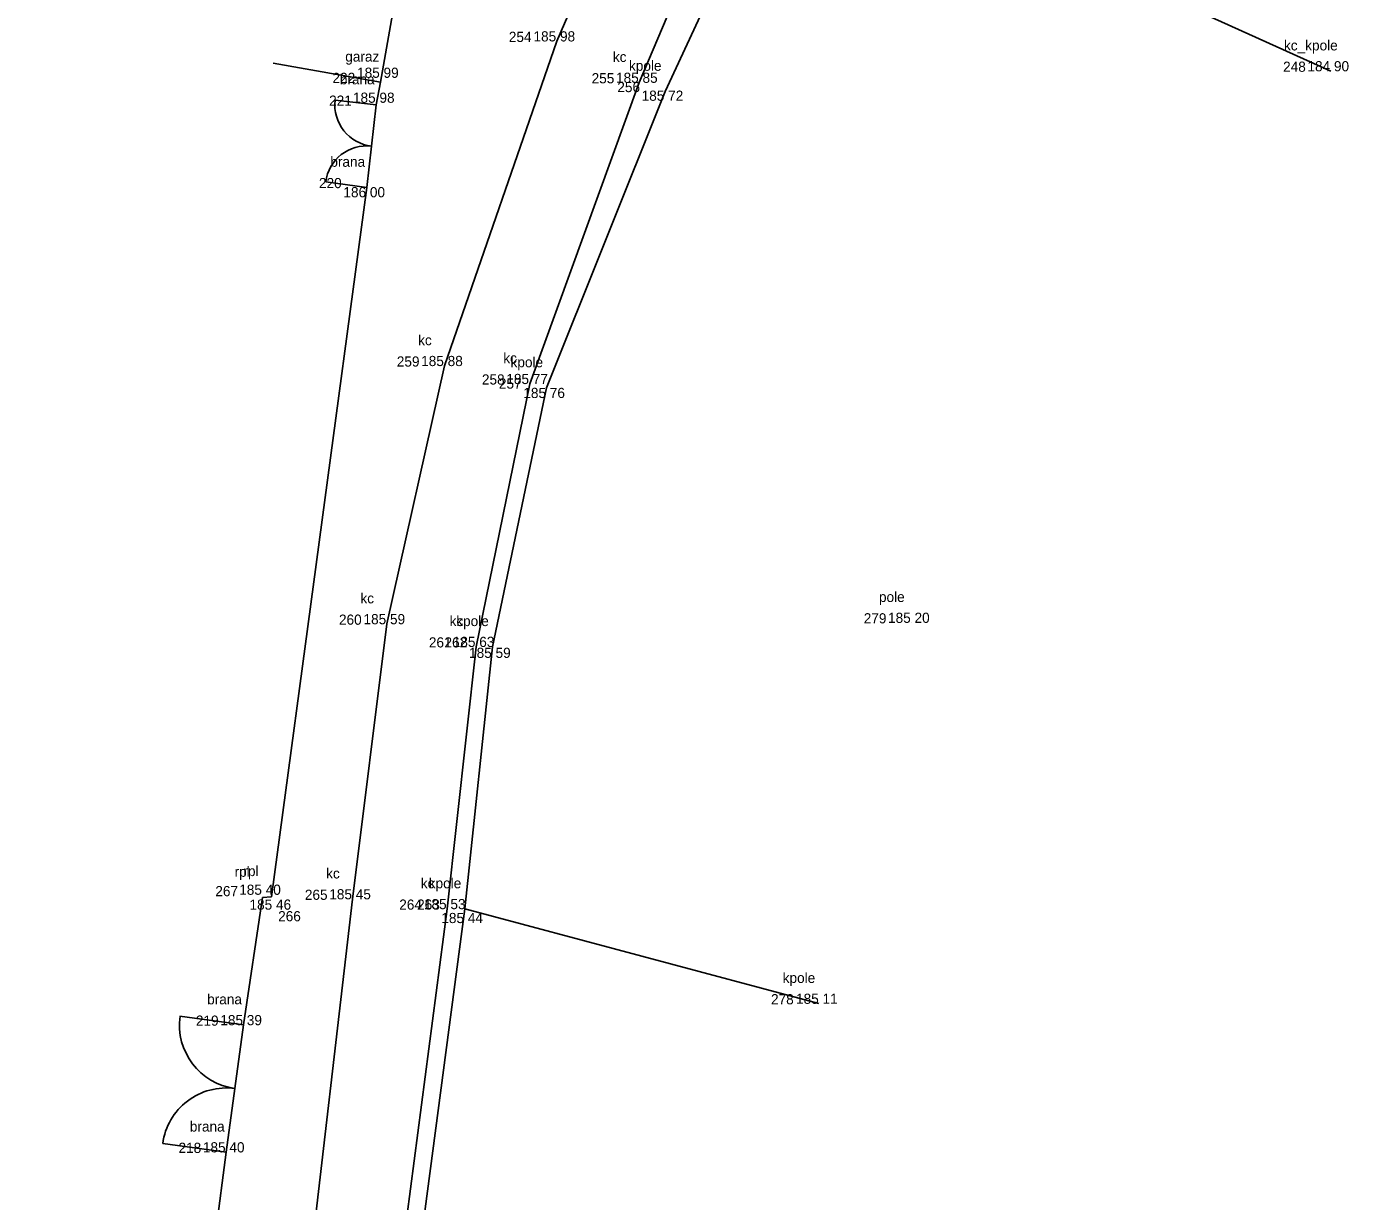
# Model space of a CAD drawing. Extents: x -598527 to -598215, y -1172822 to -1172560.
# Drawn here: x -598268.17 to -598229.21, y -1172645.27 to -1172610.63 of the extents above; entities that cross this region are included whole.
import ezdxf

# ---------------------------------------------------------------- set-up
doc = ezdxf.new("R2010")
doc.units = 0
for name, color, linetype in [('Body', 7, 'Continuous'), ('Body čísla', 7, 'Continuous'), ('Kody', 7, 'Continuous'), ('Kraj pole', 7, 'Continuous'), ('PATTERN_CLASS', 7, 'Continuous'), ('Ploty', 7, 'Continuous'), ('Výšky', 7, 'Continuous')]:
    doc.layers.add(name, color=color, linetype=linetype)

msp = doc.modelspace()

# ---------------------------------------------------------------- linework, layer by layer
at = {"layer": 'Body'}
for p, q in [((-598252.54, -1172611.06), (-598252.54, -1172611.06)), ((-598229.73, -1172611.94), (-598229.73, -1172611.94)), ((-598257.74, -1172612.27), (-598257.74, -1172612.27)), ((-598250.11, -1172612.28), (-598250.11, -1172612.28)), ((-598249.35, -1172612.54), (-598249.35, -1172612.54)), ((-598257.86, -1172612.94), (-598257.86, -1172612.94)), ((-598258.14, -1172615.37), (-598258.14, -1172615.37)), ((-598255.85, -1172620.63), (-598255.85, -1172620.63)), ((-598253.34, -1172621.16), (-598253.34, -1172621.16)), ((-598252.84, -1172621.28), (-598252.84, -1172621.28)), ((-598257.55, -1172628.24), (-598257.55, -1172628.24)), ((-598242.09, -1172628.2), (-598242.09, -1172628.2)), ((-598254.92, -1172628.91), (-598254.92, -1172628.91)), ((-598254.44, -1172628.91), (-598254.44, -1172628.91)), ((-598261.21, -1172636.3), (-598261.21, -1172636.3)), ((-598260.95, -1172636.28), (-598260.95, -1172636.28)), ((-598258.56, -1172636.35), (-598258.56, -1172636.35)), ((-598255.77, -1172636.64), (-598255.77, -1172636.64)), ((-598255.25, -1172636.64), (-598255.25, -1172636.64)), ((-598244.82, -1172639.43), (-598244.82, -1172639.43)), ((-598261.77, -1172640.06), (-598261.77, -1172640.06)), ((-598262.28, -1172643.81), (-598262.28, -1172643.81))]:
    msp.add_line(p, q, dxfattribs=at)
at = {"layer": 'Kraj pole'}
for p, q in [((-598249.35, -1172612.54), (-598245.7, -1172604.72)), ((-598252.84, -1172621.28), (-598249.35, -1172612.54)), ((-598254.44, -1172628.91), (-598252.84, -1172621.28)), ((-598255.25, -1172636.64), (-598254.44, -1172628.91)), ((-598256.79, -1172648.24), (-598255.25, -1172636.64)), ((-598255.25, -1172636.64), (-598244.82, -1172639.43))]:
    msp.add_line(p, q, dxfattribs=at)
at = {"layer": 'PATTERN_CLASS'}
for p, q in [((-598257.74, -1172612.27), (-598257.23, -1172609.4)), ((-598257.74, -1172612.27), (-598260.896, -1172611.709)), ((-598253.34, -1172621.16), (-598250.11, -1172612.28))]:
    msp.add_line(p, q, dxfattribs=at)
for points in [[(-598268.17, -1172706.75), (-598265.5, -1172685.75), (-598263.77, -1172672.23), (-598261.78, -1172661.56), (-598259.91, -1172647.93), (-598258.56, -1172636.35), (-598257.55, -1172628.24), (-598255.85, -1172620.63), (-598252.54, -1172611.06), (-598250.18, -1172605.62), (-598248.3, -1172599.38), (-598247.28, -1172594.11), (-598247.12, -1172592.75), (-598247.32, -1172591.46), (-598247.682, -1172590.57), (-598248.25, -1172589.72), (-598249.298, -1172588.918), (-598249.871, -1172588.59), (-598250.6, -1172588.3), (-598252.47, -1172587.89)], [(-598250.11, -1172612.28), (-598247.61, -1172606.36), (-598246.923, -1172605.269), (-598246.42, -1172604.864), (-598245.775, -1172604.644), (-598245.325, -1172604.707), (-598243.43, -1172605.57), (-598236.98, -1172608.66), (-598229.73, -1172611.94)], [(-598253.34, -1172621.16), (-598254.92, -1172628.91), (-598255.77, -1172636.64), (-598257.28, -1172648.19), (-598259.24, -1172661.8), (-598261.36, -1172673.07), (-598262.76, -1172685.61)]]:
    msp.add_lwpolyline(points, dxfattribs=at)
at = {"layer": 'Ploty'}
for p, q in [((-598257.86, -1172612.94), (-598257.74, -1172612.27)), ((-598257.86, -1172612.94), (-598259.075, -1172612.8)), ((-598258.14, -1172615.37), (-598257.86, -1172612.94)), ((-598258.14, -1172615.37), (-598259.352, -1172615.207)), ((-598260.95, -1172636.28), (-598258.14, -1172615.37)), ((-598261.77, -1172640.06), (-598261.21, -1172636.3)), ((-598260.95, -1172636.28), (-598261.21, -1172636.3)), ((-598261.77, -1172640.06), (-598263.645, -1172639.805)), ((-598262.28, -1172643.81), (-598261.77, -1172640.06)), ((-598262.28, -1172643.81), (-598264.155, -1172643.555)), ((-598262.77, -1172647.51), (-598262.28, -1172643.81))]:
    msp.add_line(p, q, dxfattribs=at)
for centre, radius, start, end in [((-598257.86, -1172612.94), 1.223, 173.427, 263.427), ((-598258.14, -1172615.37), 1.223, 83.427, 172.3461), ((-598261.77, -1172640.06), 1.892, 172.2553, 262.2553), ((-598262.28, -1172643.81), 1.892, 82.2553, 172.2553)]:
    msp.add_arc(centre, radius, start, end, dxfattribs=at)

# ---------------------------------------------------------------- texts
at = {"layer": 'Body čísla'}
for s, p in [('254', (-598253.954, -1172611.083)), ('248', (-598231.138, -1172611.963)), ('222', (-598259.151, -1172612.293)), ('255', (-598251.515, -1172612.303)), ('256', (-598250.757, -1172612.563)), ('221', (-598259.251, -1172612.963)), ('220', (-598259.55, -1172615.393)), ('259', (-598257.256, -1172620.653)), ('258', (-598254.748, -1172621.183)), ('257', (-598254.248, -1172621.303)), ('260', (-598258.96, -1172628.263)), ('279', (-598243.496, -1172628.223)), ('261', (-598256.311, -1172628.933)), ('262', (-598255.851, -1172628.933)), ('267', (-598262.604, -1172636.266)), ('265', (-598259.965, -1172636.373)), ('266', (-598260.752, -1172637.005)), ('264', (-598257.184, -1172636.663)), ('263', (-598256.657, -1172636.663)), ('278', (-598246.228, -1172639.453)), ('219', (-598263.176, -1172640.083)), ('218', (-598263.688, -1172643.833))]:
    msp.add_text(s, height=0.3, dxfattribs=at).set_placement(p)
at = {"layer": 'Kody'}
for s, p in [('kc', (-598250.888, -1172611.673)), ('kc_kpole', (-598231.111, -1172611.333)), ('garaz', (-598258.775, -1172611.663)), ('kpole', (-598250.414, -1172611.933)), ('brana', (-598258.935, -1172612.333)), ('brana', (-598259.215, -1172614.763)), ('kc', (-598256.628, -1172620.023)), ('kc', (-598254.118, -1172620.553)), ('kpole', (-598253.904, -1172620.673)), ('kc', (-598258.328, -1172627.633)), ('pole', (-598243.047, -1172627.593)), ('kc', (-598255.698, -1172628.303)), ('kpole', (-598255.504, -1172628.303)), ('rpl', (-598262.036, -1172635.693)), ('rpl', (-598261.776, -1172635.673)), ('kc', (-598259.338, -1172635.743)), ('kc', (-598256.548, -1172636.033)), ('kpole', (-598256.314, -1172636.033)), ('kpole', (-598245.884, -1172638.823)), ('brana', (-598262.845, -1172639.453)), ('brana', (-598263.355, -1172643.203))]:
    msp.add_text(s, height=0.3, dxfattribs=at).set_placement(p)
at = {"layer": 'Výšky'}
for s, p in [('185 98', (-598253.228, -1172611.068)), ('184 90', (-598230.42, -1172611.948)), ('185 99', (-598258.427, -1172612.14)), ('185 85', (-598250.796, -1172612.288)), ('185 72', (-598250.041, -1172612.817)), ('185 98', (-598258.548, -1172612.876)), ('186 00', (-598258.83, -1172615.662)), ('185 88', (-598256.538, -1172620.638)), ('185 77', (-598254.029, -1172621.168)), ('185 76', (-598253.528, -1172621.58)), ('185 59', (-598258.237, -1172628.248)), ('185 20', (-598242.78, -1172628.208)), ('185 63', (-598255.607, -1172628.918)), ('185 59', (-598255.127, -1172629.241)), ('185 40', (-598261.9, -1172636.224)), ('185 45', (-598259.246, -1172636.358)), ('185 46', (-598261.597, -1172636.663)), ('185 53', (-598256.457, -1172636.648)), ('185 44', (-598255.944, -1172637.058)), ('185 11', (-598245.491, -1172639.438)), ('185 39', (-598262.457, -1172640.068)), ('185 40', (-598262.97, -1172643.818))]:
    msp.add_text(s, height=0.3, dxfattribs=at).set_placement(p)

doc.saveas('drawing.dxf')
